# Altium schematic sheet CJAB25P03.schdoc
size 127 x 101 mm
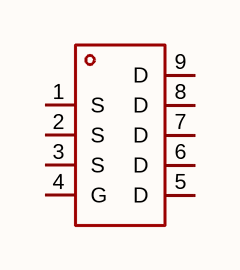
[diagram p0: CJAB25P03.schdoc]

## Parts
Q?  cjab25p03  [PDFNWB-8_L3.0-W3.0-P0.65-BL]  (value not drawn)

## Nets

Not connected (* = marked no-connect by the designer): Q? 1(S) 2(S) 3(S) 4(G) 5(D) 6(D) 7(D) 8(D) 9(D)

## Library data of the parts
Q? = cjab25p03: 数量:1个P沟道;漏源电压(Vdss):30V;连续漏极电流(Id):25A;导通电阻(RDS(on)):20mΩ@10V;耗散功率(Pd):3W;阈值电压(Vgs(th)):1V;; Manufacturer: CJ(江苏长电/长晶); AddInBom: yes; ModelId: 25c07daa3c6f4a09b1bedbcc3b730fbb; ModelName: PDFNWB-8_L3.0-W3.0-H0.8-P0.65-BL; ModelTransform: 122.047,129.921,0,180,0,0,0,0,0; Number: 1个P沟道; Drain to Source Voltage: 30V; Current - Continuous Drain(Id): 25A; Pd - Power Dissipation: 3W; Gate Threshold Voltage (Vgs(th)): 1V; Gate Charge(Qg): 30nC@10V; Input Capacitance(Ciss): 1.7nF; Reverse Transfer Capacitance (Crss@Vds): 205pF; Type: P沟道; Output Capacitance(Coss): 296pF; Vgs: ±20V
